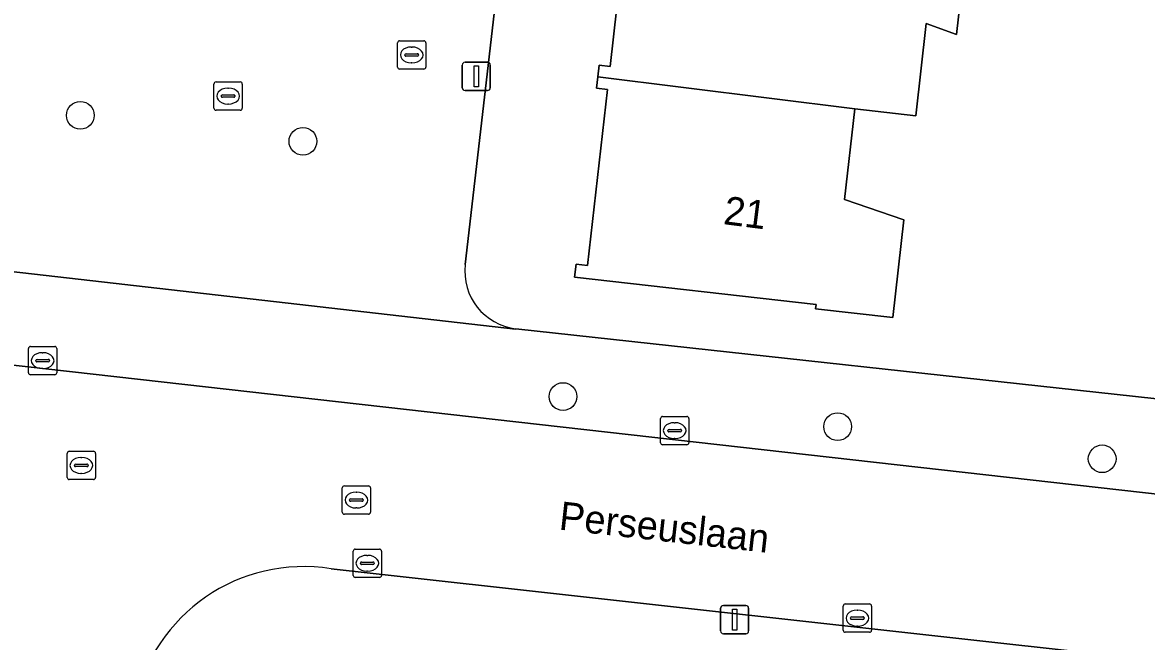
# Model space of a CAD drawing. Extents: x 162396 to 163643, y 386452 to 387406.
# Drawn here: x 162578.45 to 162618.15, y 386535.7 to 386557.56 of the extents above; entities that cross this region are included whole.
import ezdxf

# ---------------------------------------------------------------- set-up
doc = ezdxf.new("R2010")
doc.units = 0
for name, color, linetype in [('IMGEO_Boom', 7, 'Continuous'), ('IMGEO_Erf', 7, 'Continuous'), ('IMGEO_Kolk', 7, 'Continuous'), ('IMGEO_Lichtmast', 7, 'Continuous'), ('IMGEO_Openbare_ruimte_label', 7, 'Continuous'), ('IMGEO_Pand', 7, 'Continuous'), ('IMGEO_Pand_nummerreeks', 7, 'Continuous'), ('IMGEO_Rijbaan_lokaal_open', 7, 'Continuous'), ('IMGEO_Rioolput', 7, 'Continuous'), ('IMGEO_Voetpad_open', 7, 'Continuous')]:
    doc.layers.add(name, color=color, linetype=linetype)

msp = doc.modelspace()

# ---------------------------------------------------------------- linework, layer by layer
at = {"layer": 'IMGEO_Boom'}
for centre in [(162580.498, 386554.277), (162588.355, 386553.362), (162597.543, 386544.351), (162607.241, 386543.29), (162616.582, 386542.154)]:
    msp.add_circle(centre, 0.489, dxfattribs=at)
at = {"layer": 'IMGEO_Erf'}
for points in [[(162621.065, 386555.69), (162618.776, 386555.914), (162619.21, 386560.374), (162621.499, 386560.15), (162621.836, 386562.28), (162619.504, 386562.535), (162620.011, 386567.17), (162622.027, 386566.95), (162622.267, 386568.894), (162620.254, 386569.106), (162620.743, 386573.743), (162622.81, 386573.525), (162623.054, 386576.032), (162599.022, 386578.467), (162599.075, 386579.017), (162597.565, 386579.171), (162594.088, 386549.01)], [(162611.899, 386561.193), (162611.439, 386557.132), (162610.366, 386557.515), (162609.997, 386554.26), (162607.847, 386554.503), (162607.485, 386551.306), (162609.575, 386550.589), (162609.185, 386547.14), (162606.459, 386547.449), (162606.476, 386547.598), (162597.953, 386548.563), (162598.005, 386549.021), (162598.407, 386548.976), (162599.11, 386555.19), (162598.729, 386555.233), (162598.775, 386555.64), (162598.822, 386556.047), (162599.206, 386556.003), (162599.906, 386562.187)], [(162595.881, 386546.745), (162619.803, 386544.13), (162619.88, 386544.729), (162619.943, 386545.225), (162620.618, 386551.111), (162621.065, 386555.69)]]:
    msp.add_lwpolyline(points, dxfattribs=at)
msp.add_arc((162596.118, 386548.775), 2.044, 173.3906, 263.3405, dxfattribs=at)
at = {"layer": 'IMGEO_Kolk'}
for p, q in [((162585.215, 386554.532), (162585.215, 386555.384)), ((162585.29, 386555.458), (162586.142, 386555.458)), ((162585.703, 386555.238), (162585.728, 386555.238)), ((162586.216, 386555.384), (162586.216, 386554.532)), ((162585.474, 386554.952), (162585.474, 386554.964)), ((162585.912, 386554.915), (162585.514, 386554.915)), ((162585.517, 386555.001), (162585.915, 386555.001)), ((162585.958, 386554.964), (162585.958, 386554.952)), ((162586.142, 386554.458), (162585.29, 386554.458)), ((162585.726, 386554.678), (162585.701, 386554.678)), ((162578.664, 386545.194), (162578.664, 386546.046)), ((162578.739, 386546.12), (162579.591, 386546.12)), ((162579.665, 386546.046), (162579.665, 386545.194)), ((162578.923, 386545.614), (162578.923, 386545.626)), ((162579.361, 386545.577), (162578.963, 386545.577)), ((162578.966, 386545.663), (162579.364, 386545.663)), ((162579.152, 386545.9), (162579.177, 386545.9)), ((162579.407, 386545.626), (162579.407, 386545.614)), ((162579.175, 386545.34), (162579.15, 386545.34)), ((162579.591, 386545.12), (162578.739, 386545.12)), ((162600.984, 386542.723), (162600.984, 386543.575)), ((162601.059, 386543.649), (162601.911, 386543.649)), ((162601.985, 386543.575), (162601.985, 386542.723)), ((162601.286, 386543.192), (162601.684, 386543.192)), ((162601.472, 386543.429), (162601.497, 386543.429)), ((162601.243, 386543.143), (162601.243, 386543.155)), ((162601.681, 386543.106), (162601.283, 386543.106)), ((162601.495, 386542.869), (162601.47, 386542.869)), ((162601.727, 386543.155), (162601.727, 386543.143)), ((162601.911, 386542.649), (162601.059, 386542.649)), ((162590.131, 386538.04), (162590.131, 386538.892)), ((162590.206, 386538.966), (162591.058, 386538.966)), ((162591.132, 386538.892), (162591.132, 386538.04)), ((162590.39, 386538.46), (162590.39, 386538.472)), ((162590.828, 386538.423), (162590.43, 386538.423)), ((162590.433, 386538.509), (162590.831, 386538.509)), ((162590.619, 386538.746), (162590.644, 386538.746)), ((162590.874, 386538.472), (162590.874, 386538.46)), ((162590.642, 386538.186), (162590.617, 386538.186)), ((162591.058, 386537.966), (162590.206, 386537.966)), ((162607.436, 386536.104), (162607.436, 386536.956)), ((162607.511, 386537.03), (162608.363, 386537.03)), ((162608.437, 386536.956), (162608.437, 386536.104)), ((162607.695, 386536.524), (162607.695, 386536.536)), ((162608.133, 386536.487), (162607.735, 386536.487)), ((162607.738, 386536.573), (162608.136, 386536.573)), ((162607.924, 386536.81), (162607.949, 386536.81)), ((162608.179, 386536.536), (162608.179, 386536.524)), ((162608.363, 386536.03), (162607.511, 386536.03)), ((162607.947, 386536.25), (162607.922, 386536.25))]:
    msp.add_line(p, q, dxfattribs=at)
for points in [[(162585.215, 386554.532), (162585.215, 386555.384)], [(162585.29, 386555.458), (162586.142, 386555.458)], [(162586.216, 386555.384), (162586.216, 386554.532)], [(162586.142, 386554.458), (162585.29, 386554.458)], [(162578.664, 386545.194), (162578.664, 386546.046)], [(162578.739, 386546.12), (162579.591, 386546.12)], [(162579.665, 386546.046), (162579.665, 386545.194)], [(162579.591, 386545.12), (162578.739, 386545.12)], [(162600.984, 386542.723), (162600.984, 386543.575)], [(162601.059, 386543.649), (162601.911, 386543.649)], [(162601.985, 386543.575), (162601.985, 386542.723)], [(162601.911, 386542.649), (162601.059, 386542.649)], [(162590.131, 386538.04), (162590.131, 386538.892)], [(162590.206, 386538.966), (162591.058, 386538.966)], [(162591.132, 386538.892), (162591.132, 386538.04)], [(162591.058, 386537.966), (162590.206, 386537.966)], [(162607.436, 386536.104), (162607.436, 386536.956)], [(162607.511, 386537.03), (162608.363, 386537.03)], [(162608.437, 386536.956), (162608.437, 386536.104)], [(162608.363, 386536.03), (162607.511, 386536.03)]]:
    msp.add_lwpolyline(points, dxfattribs=at)
for centre, radius, start, end in [((162585.292, 386555.382), 0.0765, 91.552, 178.448), ((162585.292, 386555.382), 0.0765, 91.552, 178.448), ((162586.14, 386555.382), 0.0765, 1.552, 88.448), ((162586.14, 386555.382), 0.0765, 1.552, 88.448), ((162585.514, 386554.961), 0.0403, 85.8775, 175.7526), ((162585.511, 386554.951), 0.0366, 178.938, 274.7102), ((162585.915, 386554.958), 0.043, 264.8664, 352.4533), ((162585.919, 386554.963), 0.0386, 1.7309, 96.639), ((162585.292, 386554.534), 0.0765, 181.552, 268.448), ((162585.292, 386554.534), 0.0765, 181.552, 268.448), ((162586.14, 386554.534), 0.0765, 271.552, 358.448), ((162586.14, 386554.534), 0.0765, 271.552, 358.448), ((162578.741, 386546.044), 0.0765, 91.552, 178.448), ((162578.741, 386546.044), 0.0765, 91.552, 178.448), ((162579.589, 386546.044), 0.0765, 1.552, 88.448), ((162579.589, 386546.044), 0.0765, 1.552, 88.448), ((162578.963, 386545.623), 0.0403, 85.8775, 175.7526), ((162578.96, 386545.613), 0.0366, 178.938, 274.7102), ((162579.364, 386545.62), 0.043, 264.8664, 352.4533), ((162579.368, 386545.625), 0.0386, 1.7309, 96.639), ((162578.741, 386545.196), 0.0765, 181.552, 268.448), ((162578.741, 386545.196), 0.0765, 181.552, 268.448), ((162579.589, 386545.196), 0.0765, 271.552, 358.448), ((162579.589, 386545.196), 0.0765, 271.552, 358.448), ((162601.061, 386543.573), 0.0765, 91.552, 178.448), ((162601.061, 386543.573), 0.0765, 91.552, 178.448), ((162601.909, 386543.573), 0.0765, 1.552, 88.448), ((162601.909, 386543.573), 0.0765, 1.552, 88.448), ((162601.283, 386543.152), 0.0403, 85.8775, 175.7526), ((162601.688, 386543.154), 0.0386, 1.7309, 96.639), ((162601.28, 386543.142), 0.0366, 178.938, 274.7102), ((162601.684, 386543.149), 0.043, 264.8664, 352.4533), ((162601.061, 386542.725), 0.0765, 181.552, 268.448), ((162601.061, 386542.725), 0.0765, 181.552, 268.448), ((162601.909, 386542.725), 0.0765, 271.552, 358.448), ((162601.909, 386542.725), 0.0765, 271.552, 358.448), ((162590.208, 386538.89), 0.0765, 91.552, 178.448), ((162590.208, 386538.89), 0.0765, 91.552, 178.448), ((162591.056, 386538.89), 0.0765, 1.552, 88.448), ((162591.056, 386538.89), 0.0765, 1.552, 88.448), ((162590.43, 386538.469), 0.0403, 85.8775, 175.7526), ((162590.427, 386538.459), 0.0366, 178.938, 274.7102), ((162590.831, 386538.466), 0.043, 264.8664, 352.4533), ((162590.835, 386538.471), 0.0386, 1.7309, 96.639), ((162590.208, 386538.042), 0.0765, 181.552, 268.448), ((162590.208, 386538.042), 0.0765, 181.552, 268.448), ((162591.056, 386538.042), 0.0765, 271.552, 358.448), ((162591.056, 386538.042), 0.0765, 271.552, 358.448), ((162607.513, 386536.954), 0.0765, 91.552, 178.448), ((162607.513, 386536.954), 0.0765, 91.552, 178.448), ((162608.361, 386536.954), 0.0765, 1.552, 88.448), ((162608.361, 386536.954), 0.0765, 1.552, 88.448), ((162607.735, 386536.533), 0.0403, 85.8775, 175.7526), ((162607.732, 386536.523), 0.0366, 178.938, 274.7102), ((162608.136, 386536.53), 0.043, 264.8664, 352.4533), ((162608.14, 386536.535), 0.0386, 1.7309, 96.639), ((162607.513, 386536.106), 0.0765, 181.552, 268.448), ((162607.513, 386536.106), 0.0765, 181.552, 268.448), ((162608.361, 386536.106), 0.0765, 271.552, 358.448), ((162608.361, 386536.106), 0.0765, 271.552, 358.448)]:
    msp.add_arc(centre, radius, start, end, dxfattribs=at)
for centre, major_axis, ratio, start_param, end_param in [((162585.702, 386554.958), (-0.387, 0.002), 0.722429, 4.712389, 7.853982), ((162585.727, 386554.958), (-0.39, 0.002), 0.717154, 1.570796, 4.712389), ((162579.151, 386545.62), (-0.387, 0.002), 0.722429, 4.712389, 7.853982), ((162579.176, 386545.62), (-0.39, 0.002), 0.717154, 1.570796, 4.712389), ((162601.471, 386543.149), (-0.387, 0.002), 0.722429, 4.712389, 7.853982), ((162601.496, 386543.149), (-0.39, 0.002), 0.717154, 1.570796, 4.712389), ((162590.618, 386538.466), (-0.387, 0.002), 0.722429, 4.712389, 7.853982), ((162590.643, 386538.466), (-0.39, 0.002), 0.717154, 1.570796, 4.712389), ((162607.923, 386536.53), (-0.387, 0.002), 0.722429, 4.712389, 7.853982), ((162607.948, 386536.53), (-0.39, 0.002), 0.717154, 1.570796, 4.712389)]:
    msp.add_ellipse(centre, major_axis=major_axis, ratio=ratio, start_param=start_param, end_param=end_param, dxfattribs=at)
at = {"layer": 'IMGEO_Lichtmast'}
for p, q in [((162593.983, 386555.254), (162593.983, 386556.054)), ((162593.983, 386556.054), (162593.983, 386555.254)), ((162594.083, 386556.154), (162594.873, 386556.154)), ((162594.873, 386556.154), (162594.083, 386556.154)), ((162594.973, 386556.054), (162594.973, 386555.254)), ((162594.973, 386555.254), (162594.973, 386556.054)), ((162594.873, 386555.154), (162594.083, 386555.154)), ((162594.083, 386555.154), (162594.873, 386555.154)), ((162603.105, 386536.077), (162603.105, 386536.877)), ((162603.105, 386536.877), (162603.105, 386536.077)), ((162603.205, 386536.977), (162603.995, 386536.977)), ((162603.995, 386536.977), (162603.205, 386536.977)), ((162604.095, 386536.877), (162604.095, 386536.077)), ((162604.095, 386536.077), (162604.095, 386536.877)), ((162603.995, 386535.977), (162603.205, 386535.977)), ((162603.205, 386535.977), (162603.995, 386535.977))]:
    msp.add_line(p, q, dxfattribs=at)
for points in [[(162594.403, 386556.029), (162594.553, 386556.029), (162594.553, 386555.279), (162594.403, 386555.279), (162594.403, 386556.029)], [(162603.525, 386536.852), (162603.675, 386536.852), (162603.675, 386536.102), (162603.525, 386536.102), (162603.525, 386536.852)]]:
    msp.add_lwpolyline(points, dxfattribs=at)
for centre, start, end in [((162594.083, 386556.054), 90, 180), ((162594.083, 386556.054), 90, 180), ((162594.873, 386556.054), 0, 90), ((162594.873, 386556.054), 360, 90), ((162594.083, 386555.254), 180, 270), ((162594.083, 386555.254), 180, 270), ((162594.873, 386555.254), 270, 0), ((162594.873, 386555.254), 270, 0), ((162603.205, 386536.877), 90, 180), ((162603.205, 386536.877), 90, 180), ((162603.995, 386536.877), 0, 90), ((162603.995, 386536.877), 360, 90), ((162603.205, 386536.077), 180, 270), ((162603.205, 386536.077), 180, 270), ((162603.995, 386536.077), 270, 0), ((162603.995, 386536.077), 270, 0)]:
    msp.add_arc(centre, 0.1, start, end, dxfattribs=at)
at = {"layer": 'IMGEO_Pand'}
for points in [[(162607.847, 386554.503), (162609.997, 386554.26), (162610.366, 386557.515), (162611.439, 386557.132), (162611.899, 386561.193), (162610.753, 386561.263), (162599.605, 386562.578), (162599.565, 386562.226), (162599.906, 386562.187), (162599.206, 386556.003), (162598.822, 386556.047), (162598.775, 386555.64)], [(162598.775, 386555.64), (162598.729, 386555.233), (162599.11, 386555.19), (162598.407, 386548.976), (162598.005, 386549.021), (162597.953, 386548.563), (162606.476, 386547.598), (162606.459, 386547.449), (162609.185, 386547.14), (162609.575, 386550.589), (162607.485, 386551.306), (162607.847, 386554.503)]]:
    msp.add_lwpolyline(points, close=True, dxfattribs=at)
at = {"layer": 'IMGEO_Rijbaan_lokaal_open'}
for points in [[(162643.999, 386538.038), (162577.823, 386545.5), (162574.232, 386513.437), (162573.651, 386507.959), (162573.117, 386503.574)], [(162589.353, 386538.269), (162618.838, 386534.995), (162624.275, 386534.399), (162624.79, 386534.354), (162645.885, 386532.284), (162646.614, 386538.331)]]:
    msp.add_lwpolyline(points, dxfattribs=at)
msp.add_arc((162588.374, 386532.27), 6.079, 80.729, 168.5066, dxfattribs=at)
at = {"layer": 'IMGEO_Rioolput'}
for p, q in [((162591.697, 386555.984), (162591.697, 386556.836)), ((162591.772, 386556.91), (162592.624, 386556.91)), ((162592.185, 386556.69), (162592.21, 386556.69)), ((162592.698, 386556.836), (162592.698, 386555.984)), ((162591.956, 386556.404), (162591.956, 386556.416)), ((162592.394, 386556.367), (162591.996, 386556.367)), ((162591.999, 386556.453), (162592.397, 386556.453)), ((162592.44, 386556.416), (162592.44, 386556.404)), ((162592.624, 386555.91), (162591.772, 386555.91)), ((162592.208, 386556.13), (162592.183, 386556.13)), ((162580.106, 386542.42), (162580.958, 386542.42)), ((162580.031, 386541.494), (162580.031, 386542.346)), ((162580.519, 386542.2), (162580.544, 386542.2)), ((162581.032, 386542.346), (162581.032, 386541.494)), ((162580.29, 386541.914), (162580.29, 386541.926)), ((162580.728, 386541.877), (162580.33, 386541.877)), ((162580.333, 386541.963), (162580.731, 386541.963)), ((162580.542, 386541.64), (162580.517, 386541.64)), ((162580.774, 386541.926), (162580.774, 386541.914)), ((162580.958, 386541.42), (162580.106, 386541.42)), ((162589.82, 386541.198), (162590.672, 386541.198)), ((162589.745, 386540.272), (162589.745, 386541.124)), ((162590.233, 386540.978), (162590.258, 386540.978)), ((162590.746, 386541.124), (162590.746, 386540.272)), ((162590.004, 386540.692), (162590.004, 386540.704)), ((162590.442, 386540.655), (162590.044, 386540.655)), ((162590.047, 386540.741), (162590.445, 386540.741)), ((162590.256, 386540.418), (162590.231, 386540.418)), ((162590.488, 386540.704), (162590.488, 386540.692)), ((162590.672, 386540.198), (162589.82, 386540.198))]:
    msp.add_line(p, q, dxfattribs=at)
for points in [[(162591.697, 386555.984), (162591.697, 386556.836)], [(162591.772, 386556.91), (162592.624, 386556.91)], [(162592.698, 386556.836), (162592.698, 386555.984)], [(162592.624, 386555.91), (162591.772, 386555.91)], [(162580.106, 386542.42), (162580.958, 386542.42)], [(162580.031, 386541.494), (162580.031, 386542.346)], [(162581.032, 386542.346), (162581.032, 386541.494)], [(162580.958, 386541.42), (162580.106, 386541.42)], [(162589.82, 386541.198), (162590.672, 386541.198)], [(162589.745, 386540.272), (162589.745, 386541.124)], [(162590.746, 386541.124), (162590.746, 386540.272)], [(162590.672, 386540.198), (162589.82, 386540.198)]]:
    msp.add_lwpolyline(points, dxfattribs=at)
for centre, radius, start, end in [((162591.774, 386556.834), 0.0765, 91.552, 178.448), ((162591.774, 386556.834), 0.0765, 91.552, 178.448), ((162592.622, 386556.834), 0.0765, 1.552, 88.448), ((162592.622, 386556.834), 0.0765, 1.552, 88.448), ((162591.996, 386556.413), 0.0403, 85.8775, 175.7526), ((162591.993, 386556.403), 0.0366, 178.938, 274.7102), ((162592.397, 386556.41), 0.043, 264.8664, 352.4533), ((162592.401, 386556.415), 0.0386, 1.7309, 96.639), ((162591.774, 386555.986), 0.0765, 181.552, 268.448), ((162591.774, 386555.986), 0.0765, 181.552, 268.448), ((162592.622, 386555.986), 0.0765, 271.552, 358.448), ((162592.622, 386555.986), 0.0765, 271.552, 358.448), ((162580.108, 386542.344), 0.0765, 91.552, 178.448), ((162580.108, 386542.344), 0.0765, 91.552, 178.448), ((162580.956, 386542.344), 0.0765, 1.552, 88.448), ((162580.956, 386542.344), 0.0765, 1.552, 88.448), ((162580.33, 386541.923), 0.0403, 85.8775, 175.7526), ((162580.327, 386541.913), 0.0366, 178.938, 274.7102), ((162580.731, 386541.92), 0.043, 264.8664, 352.4533), ((162580.735, 386541.925), 0.0386, 1.7309, 96.639), ((162580.108, 386541.496), 0.0765, 181.552, 268.448), ((162580.108, 386541.496), 0.0765, 181.552, 268.448), ((162580.956, 386541.496), 0.0765, 271.552, 358.448), ((162580.956, 386541.496), 0.0765, 271.552, 358.448), ((162589.822, 386541.122), 0.0765, 91.552, 178.448), ((162589.822, 386541.122), 0.0765, 91.552, 178.448), ((162590.67, 386541.122), 0.0765, 1.552, 88.448), ((162590.67, 386541.122), 0.0765, 1.552, 88.448), ((162590.044, 386540.701), 0.0403, 85.8775, 175.7526), ((162590.041, 386540.691), 0.0366, 178.938, 274.7102), ((162590.445, 386540.698), 0.043, 264.8664, 352.4533), ((162590.449, 386540.703), 0.0386, 1.7309, 96.639), ((162589.822, 386540.274), 0.0765, 181.552, 268.448), ((162589.822, 386540.274), 0.0765, 181.552, 268.448), ((162590.67, 386540.274), 0.0765, 271.552, 358.448), ((162590.67, 386540.274), 0.0765, 271.552, 358.448)]:
    msp.add_arc(centre, radius, start, end, dxfattribs=at)
for centre, major_axis, ratio, start_param, end_param in [((162592.184, 386556.41), (-0.387, 0.002), 0.722429, 4.712389, 7.853982), ((162592.209, 386556.41), (-0.39, 0.002), 0.717154, 1.570796, 4.712389), ((162580.518, 386541.92), (-0.387, 0.002), 0.722429, 4.712389, 7.853982), ((162580.543, 386541.92), (-0.39, 0.002), 0.717154, 1.570796, 4.712389), ((162590.232, 386540.698), (-0.387, 0.002), 0.722429, 4.712389, 7.853982), ((162590.257, 386540.698), (-0.39, 0.002), 0.717154, 1.570796, 4.712389)]:
    msp.add_ellipse(centre, major_axis=major_axis, ratio=ratio, start_param=start_param, end_param=end_param, dxfattribs=at)
at = {"layer": 'IMGEO_Voetpad_open'}
for points in [[(162594.088, 386549.01), (162597.565, 386579.171), (162599.075, 386579.017), (162599.162, 386579.822), (162602.317, 386609.066)], [(162576.011, 386556.173), (162575.154, 386549.09), (162595.86, 386546.731), (162595.881, 386546.745)], [(162595.881, 386546.745), (162595.86, 386546.731), (162575.154, 386549.09), (162575.012, 386547.916), (162574.783, 386545.83), (162577.823, 386545.5), (162643.999, 386538.038)], [(162644.341, 386542.44), (162641.322, 386542.774), (162638.128, 386543.14), (162638.071, 386542.643), (162619.88, 386544.729), (162619.803, 386544.13), (162595.881, 386546.745)], [(162624.79, 386534.354), (162624.275, 386534.399), (162624.22, 386533.903), (162618.783, 386534.499), (162618.838, 386534.995), (162589.353, 386538.269)]]:
    msp.add_lwpolyline(points, dxfattribs=at)
for centre, radius, start, end in [((162596.118, 386548.775), 2.044, 173.3906, 263.3405), ((162588.374, 386532.27), 6.079, 80.729, 168.5066)]:
    msp.add_arc(centre, radius, start, end, dxfattribs=at)

# ---------------------------------------------------------------- texts
at = {"layer": 'IMGEO_Openbare_ruimte_label'}
msp.add_text('Perseuslaan', height=1, rotation=353.6282, dxfattribs=at).set_placement((162597.372, 386539.659))
at = {"layer": 'IMGEO_Pand_nummerreeks'}
msp.add_text('21', height=1, rotation=352.7796, dxfattribs=at).set_placement((162603.178, 386550.441))

doc.saveas('drawing.dxf')
